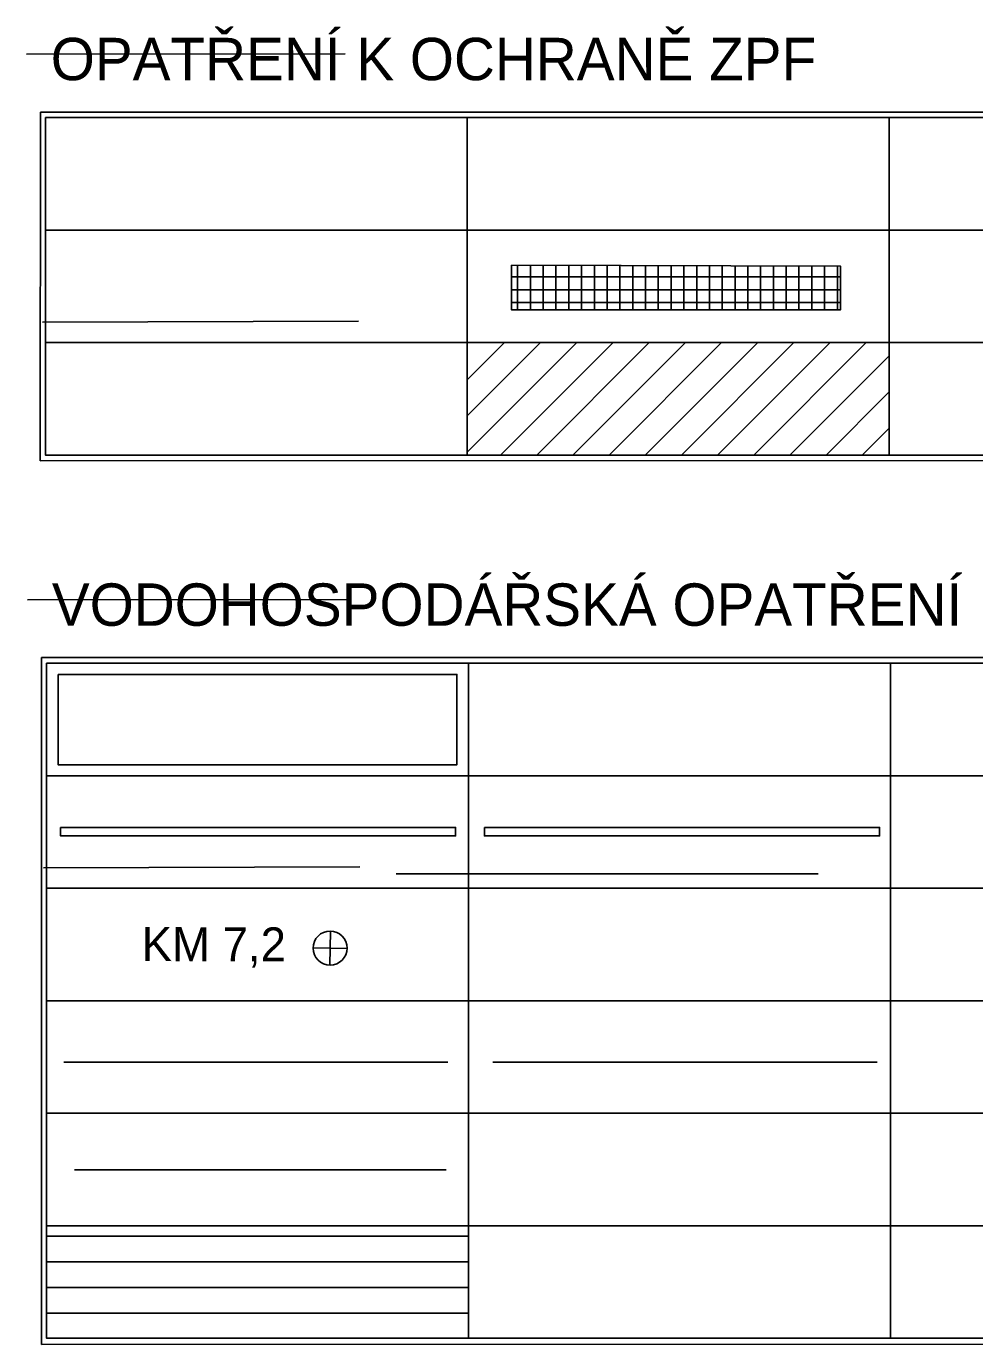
# Model space of a CAD drawing. Extents: x -478232 to -472707, y -1118753 to -1113967.
# Drawn here: x -474027 to -473657, y -1118315 to -1117800 of the extents above; entities that cross this region are included whole.
import ezdxf

# ---------------------------------------------------------------- set-up
doc = ezdxf.new("R2010")
doc.units = 0
doc.layers.add('staničení toku', color=7, linetype='Continuous')
doc.layers.add('Z_razitko', color=7, linetype='Continuous')

msp = doc.modelspace()

# ---------------------------------------------------------------- linework, layer by layer
at = {"layer": 'staničení toku'}
for p, q in [((-473908.507, -1118153.408), (-473908.785, -1118166.715)), ((-473901.992, -1118160.2), (-473915.3, -1118159.922))]:
    msp.add_line(p, q, dxfattribs=at)
msp.add_circle((-473908.646, -1118160.061), 6.655, dxfattribs=at)
at = {"layer": 'Z_razitko'}
for p, q in [((-473902.701, -1117810.494), (-474027.374, -1117810.612)), ((-474021.912, -1117833.223), (-474021.915, -1117969.616)), ((-473059.937, -1117833.223), (-474021.912, -1117833.223)), ((-473835.363, -1117910.6), (-473835.363, -1117893.082)), ((-473830.363, -1117910.6), (-473830.363, -1117893.097)), ((-473825.363, -1117910.6), (-473825.363, -1117893.112)), ((-473820.363, -1117910.6), (-473820.363, -1117893.128)), ((-473815.363, -1117910.6), (-473815.363, -1117893.143)), ((-473810.363, -1117910.6), (-473810.363, -1117893.158)), ((-473805.363, -1117910.6), (-473805.363, -1117893.174)), ((-473800.363, -1117910.6), (-473800.363, -1117893.189)), ((-473795.363, -1117910.6), (-473795.363, -1117893.204)), ((-473790.363, -1117910.6), (-473790.363, -1117893.22)), ((-473785.363, -1117910.6), (-473785.363, -1117893.235)), ((-473780.363, -1117910.6), (-473780.363, -1117893.25)), ((-473775.363, -1117910.6), (-473775.363, -1117893.266)), ((-473770.363, -1117910.6), (-473770.363, -1117893.281)), ((-473765.363, -1117910.6), (-473765.363, -1117893.296)), ((-473760.363, -1117910.6), (-473760.363, -1117893.312)), ((-473755.363, -1117910.6), (-473755.363, -1117893.327)), ((-473750.363, -1117910.6), (-473750.363, -1117893.342)), ((-473745.363, -1117910.6), (-473745.363, -1117893.358)), ((-473740.363, -1117910.6), (-473740.363, -1117893.373)), ((-473735.363, -1117910.6), (-473735.363, -1117893.388)), ((-473730.363, -1117910.6), (-473730.363, -1117893.404)), ((-473725.363, -1117910.6), (-473725.363, -1117893.419)), ((-473720.363, -1117910.6), (-473720.363, -1117893.434)), ((-473715.363, -1117910.6), (-473715.363, -1117893.45)), ((-473710.363, -1117910.6), (-473710.363, -1117893.465)), ((-473709.189, -1117897.696), (-473837.699, -1117897.696)), ((-473709.189, -1117902.696), (-473837.699, -1117902.696)), ((-473709.189, -1117907.696), (-473837.699, -1117907.696)), ((-474021.089, -1117915.396), (-473897.504, -1117915.039)), ((-473855.018, -1117966.172), (-473812.208, -1117923.363)), ((-473855.018, -1117952.03), (-473826.351, -1117923.363)), ((-473855.018, -1117937.888), (-473840.493, -1117923.363)), ((-473855.018, -1117923.746), (-473854.635, -1117923.363)), ((-473842.044, -1117967.341), (-473798.066, -1117923.363)), ((-473827.902, -1117967.341), (-473783.924, -1117923.363)), ((-473813.76, -1117967.341), (-473769.782, -1117923.363)), ((-473799.618, -1117967.341), (-473755.64, -1117923.363)), ((-473785.476, -1117967.341), (-473741.498, -1117923.363)), ((-473771.334, -1117967.341), (-473727.356, -1117923.363)), ((-473757.192, -1117967.341), (-473713.213, -1117923.363)), ((-473743.05, -1117967.341), (-473699.071, -1117923.363)), ((-473728.907, -1117967.341), (-473690.092, -1117928.525)), ((-473714.765, -1117967.341), (-473690.092, -1117942.667)), ((-473700.623, -1117967.341), (-473690.092, -1117956.809)), ((-473059.94, -1117969.131), (-474021.915, -1117969.616)), ((-473902.261, -1118023.77), (-474026.934, -1118023.888)), ((-474021.473, -1118046.499), (-474021.477, -1118315.071)), ((-473059.498, -1118046.499), (-474021.473, -1118046.499)), ((-474020.649, -1118128.672), (-473897.065, -1118128.315)), ((-473882.843, -1118130.976), (-473717.926, -1118130.976)), ((-474012.735, -1118204.646), (-473862.578, -1118204.646)), ((-473845.014, -1118204.646), (-473694.856, -1118204.646)), ((-474008.577, -1118246.8), (-473863.241, -1118246.8)), ((-473854.573, -1118272.729), (-474019.497, -1118272.729)), ((-473854.573, -1118282.729), (-474019.497, -1118282.729)), ((-473854.573, -1118292.729), (-474019.497, -1118292.729)), ((-473854.573, -1118302.729), (-474019.497, -1118302.729)), ((-473059.503, -1118314.663), (-474021.477, -1118315.071))]:
    msp.add_line(p, q, dxfattribs=at)
for points in [[(-474019.944, -1117835.403), (-473855.02, -1117835.403), (-473855.02, -1117835.403), (-473855.02, -1117879.381), (-474019.944, -1117879.381)], [(-473855.018, -1117835.405), (-473061.588, -1117835.405), (-473061.588, -1117879.385), (-473855.018, -1117879.385)], [(-473855.018, -1117835.405), (-473690.097, -1117835.405), (-473690.097, -1117835.405), (-473690.097, -1117879.385), (-473855.018, -1117879.385)], [(-473690.092, -1117835.408), (-473690.092, -1117879.387), (-473855.018, -1117879.383), (-473855.018, -1117835.405)], [(-474019.944, -1117879.381), (-473855.02, -1117879.381), (-473855.02, -1117879.381), (-473855.02, -1117923.359), (-474019.944, -1117923.359)], [(-473855.018, -1117879.383), (-473061.588, -1117879.383), (-473061.588, -1117923.363), (-473855.018, -1117923.363)], [(-473837.699, -1117893.075), (-473837.699, -1117910.6), (-473709.189, -1117910.6), (-473709.189, -1117893.468)], [(-474019.944, -1117923.359), (-473855.02, -1117923.359), (-473855.02, -1117923.359), (-473855.02, -1117967.337), (-474019.944, -1117967.337)], [(-473855.018, -1117923.361), (-473061.588, -1117923.361), (-473061.588, -1117967.341), (-473855.018, -1117967.341)], [(-474019.504, -1118048.679), (-473854.581, -1118048.679), (-473854.581, -1118048.679), (-473854.581, -1118092.657), (-474019.504, -1118092.657)], [(-473854.578, -1118048.681), (-473061.148, -1118048.681), (-473061.148, -1118092.661), (-473854.578, -1118092.661)], [(-473854.578, -1118048.681), (-473689.657, -1118048.681), (-473689.657, -1118048.681), (-473689.657, -1118092.661), (-473854.578, -1118092.661)], [(-474014.995, -1118053.101), (-473859.103, -1118053.101), (-473859.103, -1118088.37), (-474014.995, -1118088.37)], [(-474019.507, -1118092.654), (-473854.583, -1118092.654), (-473854.583, -1118092.654), (-473854.583, -1118136.632), (-474019.507, -1118136.632)], [(-473854.578, -1118092.661), (-473689.657, -1118092.661), (-473689.657, -1118092.661), (-473689.657, -1118136.64), (-473854.578, -1118136.64)], [(-473854.578, -1118092.665), (-473061.148, -1118092.665), (-473061.148, -1118136.644), (-473854.578, -1118136.644)], [(-474014.025, -1118112.886), (-473859.597, -1118112.886), (-473859.597, -1118116.191), (-474014.025, -1118116.191)], [(-473848.305, -1118112.886), (-473693.877, -1118112.886), (-473693.877, -1118116.191), (-473848.305, -1118116.191)], [(-474019.502, -1118136.64), (-473854.578, -1118136.64), (-473854.578, -1118136.64), (-473854.578, -1118180.618), (-474019.502, -1118180.618)], [(-473854.573, -1118136.647), (-473689.652, -1118136.647), (-473689.652, -1118136.647), (-473689.652, -1118180.626), (-473854.573, -1118180.626)], [(-473854.573, -1118136.65), (-473061.143, -1118136.65), (-473061.143, -1118180.63), (-473854.573, -1118180.63)], [(-474019.497, -1118180.63), (-473854.573, -1118180.63), (-473854.573, -1118180.63), (-473854.573, -1118224.608), (-474019.497, -1118224.608)], [(-473854.568, -1118180.636), (-473689.647, -1118180.636), (-473689.647, -1118180.636), (-473689.647, -1118224.616), (-473854.568, -1118224.616)], [(-473854.568, -1118180.64), (-473061.138, -1118180.64), (-473061.138, -1118224.62), (-473854.568, -1118224.62)], [(-474019.497, -1118224.608), (-473854.573, -1118224.608), (-473854.573, -1118224.608), (-473854.573, -1118268.586), (-474019.497, -1118268.586)], [(-473854.568, -1118224.614), (-473689.647, -1118224.614), (-473689.647, -1118224.614), (-473689.647, -1118268.594), (-473854.568, -1118268.594)], [(-473854.568, -1118224.618), (-473061.138, -1118224.618), (-473061.138, -1118268.598), (-473854.568, -1118268.598)], [(-474019.497, -1118268.586), (-473854.573, -1118268.586), (-473854.573, -1118268.586), (-473854.573, -1118312.564), (-474019.497, -1118312.564)], [(-473854.568, -1118268.593), (-473689.647, -1118268.593), (-473689.647, -1118268.593), (-473689.647, -1118312.572), (-473854.568, -1118312.572)], [(-473854.568, -1118268.596), (-473061.138, -1118268.596), (-473061.138, -1118312.576), (-473854.568, -1118312.576)]]:
    msp.add_lwpolyline(points, close=True, dxfattribs=at)
msp.add_lwpolyline([(-473690.092, -1117879.386), (-473690.092, -1117923.365), (-473690.092, -1117967.345)], dxfattribs=at)

# ---------------------------------------------------------------- texts
at = {"layer": 'staničení toku'}
msp.add_text('KM 7,2', height=13.31, rotation=359.87026, dxfattribs=at).set_placement((-473982.324, -1118165.141))
at = {"layer": 'Z_razitko'}
for s, p in [('OPATŘENÍ K OCHRANĚ ZPF', (-474017.84, -1117820.79)), ('VODOHOSPODÁŘSKÁ OPATŘENÍ', (-474017.4, -1118034.066))]:
    msp.add_text(s, height=16.5709, dxfattribs=at).set_placement(p)

doc.saveas('drawing.dxf')
